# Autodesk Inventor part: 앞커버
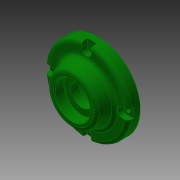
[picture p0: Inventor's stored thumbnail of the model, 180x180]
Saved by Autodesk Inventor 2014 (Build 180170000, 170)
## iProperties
Created: 2017-08
Part Number: 앞커버
Material: 알루미늄 6061
Document SubType Name: Modeling
Designer: mduedu
Density: 1 g/cm^3
Appearance: 진녹색
Author: mduedu
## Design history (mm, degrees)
sketch "스케치1"
  geometry: C1 r 35 at (0, 0); 1 further point
  constraints: 1 centre point, 1 coincident
  dimensions: "d0" = 70 diameter of C1
extrude "돌출1" new body sketch "스케치1" distance "d1" = 10; taper "d2" = 0 deg
sketch "스케치2"
  geometry: C1 r 24 at (0, 0); 1 further point
  constraints: 1 centre point, 1 coincident
  dimensions: "d3" = 48 diameter of C1
node "작업 평면1"
sketch "스케치3"
  geometry: C1 r 20 at (0, 0); 1 further point
  constraints: 1 centre point, 1 coincident
  dimensions: "d5" = 40 diameter of C1
feature "로프트1" sketch "스케치3" dims "d6" = 0, "d7" = 90 deg, "d8" = 0, "d9" = 90 deg
sketch "스케치4"
  geometry: C1 r 24 at (0, 0) reference; 1 further point
extrude "돌출2" join sketch "스케치4" distance "d10" = 8; taper "d11" = 0 deg
hole "구멍1" diameter "d14" = 40; stored, may be unused: countersink angle "d18" = 90 deg, drill point angle "d20" = 0 deg; dims "d12" = 10, "d13" = 10, "d15" = 6, "d16" = 4, "d17" = 2, "d19" = 12
hole "구멍2" diameter "d23" = 34; stored, may be unused: countersink angle "d27" = 90 deg, drill point angle "d29" = 0 deg; dims "d21" = 10, "d22" = 10, "d24" = 6, "d25" = 4, "d26" = 2, "d28" = 3
hole "구멍3" diameter "d32" = 19; stored, may be unused: countersink angle "d36" = 90 deg, drill point angle "d38" = 0 deg; dims "d30" = 10, "d31" = 10, "d33" = 6, "d34" = 4, "d35" = 2, "d37" = 3
chamfer "모따기1" distance "d39" = 1; stored, may be unused: second distance "d40" = 2, angle "d41" = 45 deg
sketch "스케치5"
  geometry: C1 r 15 at (0, 0); 1 further point
  constraints: 1 centre point, 1 coincident
  dimensions: "d42" = 30 diameter of C1
extrude "돌출3" cut sketch "스케치5" distance "d43" = 8.3; taper "d44" = 0 deg
chamfer "모따기2" distance "d47" = 0.8; stored, may be unused: second distance "d48" = 2, angle "d49" = 30 deg
fillet "모깎기1" dims "d50" = 0.3
fillet "모깎기2" dims "d51" = 0.3
fillet "모깎기3" dims "d52" = 3
fillet "모깎기4" dims "d79" = 3
sketch "스케치6" dims "d53" = 58
  geometry: 6 further points
  constraints: 2 vertical alignment, 1 coincident, 7 other
  dimensions: "d56" = 360 deg dimension on point (0, 0) point (0, 29) (derived)
sketch "스케치9" dims "d93" = 62
  geometry: C1 r 35 at (0, 0) reference; 3 further points
  constraints: 2 vertical alignment, 1 coincident, 2 other
hole "구멍6" sketch "스케치9" at (0, 31) diameter "d72" = 4.5; stored, may be unused: countersink angle "d76" = 90 deg, drill point angle "d78" = 0 deg; dims "d73" = 6, "d74" = 8, "d75" = 4.6, "d77" = 8
fillet "모깎기5" dims "d80" = 3
fillet "모깎기6" dims "d81" = 3
sketch "스케치10"
  geometry: L1 (-4, 31)-(4, 31); L2 (4, 31)-(4, 38); L3 (4, 38)-(-4, 38); L4 (-4, 38)-(-4, 31); 6 further points
  constraints: 8 end point, 2 parallel, 1 horizontal, 1 midpoint, 1 perpendicular, 4 other
  dimensions: "d98" = 7 distance of L1.end L2.end
extrude "돌출4" cut sketch "스케치10" stored distance "d88" = 10; taper "d89" = 0 deg
node "솔리드1"
pattern_circular "원형 패턴2" dims angle "d96" = 360 deg
pattern_circular "원형 패턴1" dims angle "d91" = 360 deg
other parameters: "d4" = 12
